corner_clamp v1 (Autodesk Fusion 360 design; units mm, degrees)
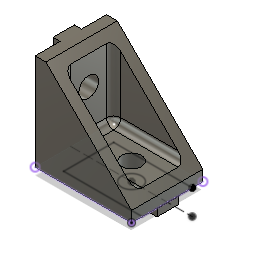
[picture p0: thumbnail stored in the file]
box_primitive "BoxPrimitive1" DistanceX 20 DistanceY 27 DistanceZ 27 OffsetDistanceX 0 OffsetDistanceY 0
sketch "Sketch5" plane through (0, 0, 35) normal (0, 0, 1) x axis (1, 0, 0)
  line L1 (-12, 0) -> (-12, 27)
  line L2 (15, 0) -> (-12, 0)
  line L3 (15, 27) -> (15, 0)
  line L4 (-12, 27) -> (15, 27)
  line L5 (15, 3) -> (-9, 27)
  line L6 (15, 27) -> (-12, 27)
  line L7 (15, 0) -> (15, 27)
  point P6 (-9, 27)
  point P7 (15, 3)
  coincident L4 P6
  coincident L3 P7
  dimension "d14" distance L1 P6 = 3
  dimension "d15" distance L2 P7 = 3
extrude "Extrude2" cut sketch "Sketch5" profile of L3 L4 L5 L6 L7 no distance stored
sketch "Sketch7" plane through (0, 0, 0) normal (0, -1, 0) x axis (1, 0, 0)
  line L1 (-12, 35) -> (15, 35)
  line L2 (-12, 15) -> (-12, 35)
  line L3 (15, 15) -> (-12, 15)
  line L4 (15, 35) -> (15, 15)
  line L5 (-12, 35) -> (15, 35)
  line L6 (15, 35) -> (15, 15)
  line L7 (15, 32) -> (-7, 32)
  line L8 (15, 18) -> (15, 32)
  line L9 (-7, 18) -> (15, 18)
  line L10 (-7, 32) -> (-7, 18)
  line L11 (22, 25) -> (-12, 25)
  circle C1 centre (5, 25) radius 2.75
  point P11 (15, 18)
  point P13 (-12, 25)
  point P15 (5, 25)
  horizontal L7
  vertical L8
  horizontal L9
  vertical L10
  coincident L6 P11
  midpoint L2 P13
  perpendicular L6 L11
  symmetric L7 L9 L11
  midpoint L11 P15
  dimension "d17" distance L7 L9 = 14
  dimension "d18" distance L2 L10 = 5
  dimension "d19" diameter C1 = 5.5
  dimension "d20" distance L10 P15 = 12
extrude "Extrude3" cut sketch "Sketch7" profile of C1 no distance stored
extrude "Extrude4" cut sketch "Sketch7" profile of L4 L6 L7 L8 L9 L10 C1 no distance stored from offset -5
sketch "Sketch8" plane through (-12, 0, 0) normal (-1, 0, 0) x axis (0, 0, 1)
  line L1 (15, 0) -> (15, 27)
  line L2 (35, 0) -> (15, 0)
  line L3 (35, 27) -> (35, 0)
  line L4 (15, 27) -> (35, 27)
  line L5 (32, 27) -> (18, 27)
  line L6 (32, 5) -> (32, 27)
  line L7 (18, 5) -> (32, 5)
  line L8 (18, 27) -> (18, 5)
  line L9 (25, 37) -> (25, 0)
  line L10 (32, 0) -> (18, 0)
  circle C1 centre (25, 17) radius 2.75
  point P6 (18, 27)
  point P10 (25, 0)
  point P14 (25, 17)
  horizontal L5
  vertical L6
  horizontal L7
  vertical L8
  coincident L4 P6
  midpoint L2 P10
  perpendicular L4 L9
  symmetric L6 L8 L9
  coincident L9 P14
  dimension "d24" distance L6 L8 = 14
  dimension "d25" distance L7 L10 = 5
  dimension "d26" diameter C1 = 5.5
  dimension "d27" distance L7 P14 = 12
extrude "Extrude5" cut sketch "Sketch8" profile of C1 no distance stored
sketch "Sketch9" plane through (0, 0, 0) normal (0, -1, 0) x axis (1, 0, 0)
  line L1 (22, 25) -> (-12, 25)
  line L2 (-12, 15) -> (-12, 35)
  line L3 (-2, 28) -> (-12, 28)
  line L4 (-2, 22) -> (-2, 28)
  line L5 (-12, 22) -> (-2, 22)
  line L6 (-12, 28) -> (-12, 22)
  line L7 (-12, 35) -> (15, 35)
  line L8 (1.5, 10) -> (1.5, 35)
  line L9 (9.5048, 28) -> (15.1398, 28)
  line L10 (9.5048, 22) -> (9.5048, 28)
  line L11 (15.1398, 22) -> (9.5048, 22)
  line L12 (15.1398, 28) -> (15.1398, 22)
  point P7 (-12, 28)
  point P13 (1.5, 35)
  point P8 (-2, 28)
  horizontal L3
  vertical L4
  horizontal L5
  vertical L6
  coincident L2 P7
  symmetric L1 L3 L5
  midpoint L7 P13
  perpendicular L7 L8
  horizontal L9
  vertical L10
  horizontal L11
  vertical L12
  collinear L3 L9
  collinear L5 L11
  dimension "d29" distance L3 L5 = 6
  dimension "d30" distance P7 P8 = 10
extrude "Extrude6" add sketch "Sketch9" profile of L1 L2 L3 L4 L5 L6 L9 L10 L11 L12 along normal blind 2
sketch "Sketch10" plane through (-12, 0, 0) normal (-1, 0, 0) x axis (0, 0, 1)
  line L1 (15, 0) -> (15, 27)
  line L2 (22, 0) -> (15, 0)
  line L3 (22, -2) -> (22, 0)
  line L4 (28, -2) -> (22, -2)
  line L5 (28, 0) -> (28, -2)
  line L6 (35, 0) -> (28, 0)
  line L7 (35, 27) -> (35, 0)
  line L8 (15, 27) -> (35, 27)
  line L9 (28, 10) -> (22, 10)
  line L10 (28, 21.5048) -> (22, 21.5048)
  line L11 (22, 0) -> (28, 0)
  line L12 (22, 10) -> (22, 0)
  line L13 (25, 34) -> (25, 0)
  line L14 (28, 0) -> (28, 10)
  line L15 (22, 21.5048) -> (22, 27.1398)
  line L16 (28, 27.1398) -> (28, 21.5048)
  line L17 (22, 27.1398) -> (28, 27.1398)
  circle C1 centre (25, 17) radius 2.75
  circle C2 centre (25, 17) radius 2.75
  dimension "d33" diameter C2 = 5.5
extrude "Extrude7" add sketch "Sketch10" profile of L8 L9 L10 L11 L12 L13 L14 L15 L16 along normal blind 2
fillet "Fillet1" radius 2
